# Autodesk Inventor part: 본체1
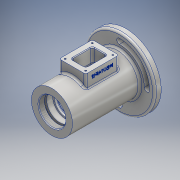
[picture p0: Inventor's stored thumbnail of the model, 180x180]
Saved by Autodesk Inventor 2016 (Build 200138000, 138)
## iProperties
Created: 2017-05
Part Number: 본체1
Material: 알루미늄 6061
Document SubType Name: Modeling
Designer: USER
Density: 2.7 g/cm^3
Appearance: 알루미늄 - 평지
Mass: 679.78 g
Surface Area: 617.383 cm^2
Volume: 251.77 cm^3
Author: USER
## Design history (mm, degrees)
sketch "스케치1"
  geometry: L1 (0, 0)-(-19.565, 0); L2 (0, 0)-(0, 31); L3 (0, 31)-(102, 31); L4 (102, 31)-(102, 53); L5 (102, 53)-(112, 53); L6 (112, 53)-(112, 31); L7 (112, 31)-(115, 31); L8 (115, 31)-(115, 0); L9 (115, 0)-(0, 0)
  constraints: 18 end point, 6 perpendicular, 2 point on line, 1 horizontal, 1 vertical
  dimensions: "d0" = 62 diameter of L3 L1; "d1" = 106 diameter of L5 L1; "d2" = 13 distance between parallel lines of L8 L4; "d3" = 3 distance of L6.end L7.end; "d4" = 115 distance between parallel lines of L2 L8
revolve "회전1" sketch "스케치1" stored, may be unused: angle "d5" = 90 deg
sketch "스케치3"
  geometry: 2 further points
  constraints: 1 coincident
hole "구멍1" sketch "스케치3" at (0, 0) diameter "d6" = 40.376; stored, may be unused: countersink angle "d10" = 90 deg, drill point angle "d12" = 118 deg; dims "d7" = 9, "d8" = 4, "d9" = 2, "d11" = 9
sketch "스케치4"
  geometry: L1 (9, 20.188)-(9, -20.188) reference; L2 (9, 0)-(9, 24); L3 (9, 24)-(12, 24); L4 (12, 24)-(12, 20); L5 (12, 20)-(21, 20); L6 (21, 20)-(21, 17.5); L7 (21, 17.5)-(24.25, 17.5); L8 (24.25, 17.5)-(24.25, 18.5); L9 (24.25, 18.5)-(26, 18.5); L10 (26, 18.5)-(26, 17.5); L11 (26, 17.5)-(37, 17.5); L12 (37, 17.5)-(37, 26); L13 (37, 26)-(75, 26); L14 (75, 26)-(75, 17.5); L15 (75, 17.5)-(86, 17.5); L16 (86, 17.5)-(86, 16.5); L17 (86, 16.5)-(91, 16.5); L18 (91, 16.5)-(91, 10); L19 (91, 10)-(93.7, 10); L20 (93.7, 10)-(93.7, 12.5); L21 (93.7, 12.5)-(100.3, 12.5); L22 (100.3, 12.5)-(101, 12.904); L23 (101, 12.904)-(101, 16); L24 (101, 16)-(115, 22); L25 (0, 0)-(-21.161, 0); L26 (0, -20.188)-(0, 20.188) reference; L27 (0, -31)-(0, 31) reference; L28 (115, 22)-(115, 0); L29 (115, -31)-(115, 31) reference; L30 (115, 0)-(9, 0)
  constraints: 52 end point, 16 perpendicular, 4 point on line, 3 vertical, 2 midpoint, 1 horizontal
  dimensions: "d13" = 48 diameter of L3 L25; "d14" = 3 distance of L2.end L3.end; "d15" = 40 diameter of L5 L25; "d16" = 35 diameter of L7 L25; "d17" = 21 distance from line of L5.end L26; "d18" = 26 distance between parallel lines of L26 L10; "d19" = 11 distance of L10.end L11.end; "d20" = 38 distance of L12.end L13.end; "d21" = 52 diameter of L13 L25; "d22" = 44 diameter of L24.end L25; "d23" = 32 diameter of L23.end L25; "d24" = 14 horizontal distance of L24.end L23.end; "d25" = 30 deg angle of L21 L22; "d26" = 33 diameter of L17 L25; "d27" = 115 distance from line of L27 L24.end; "d28" = 24 distance from line of L24.end L18; "d29" = 0.7 horizontal distance of L21.end L22.end; "d30" = 25 diameter of L21 L25; "d31" = 20 diameter of L19 L25; "d32" = 2.7 distance of L18.end L19.end; "d33" = 37 diameter of L9 L25; "d34" = 1.75 distance of L8.end L9.end; "d35" = 11 distance of L14.end L15.end
revolve "회전2" sketch "스케치4" stored, may be unused: angle "d36" = 90 deg
node "작업 평면1"
sketch "스케치5"
  geometry: L1 (20, 81)-(-20, 81); L2 (-20, 81)-(-20, 31); L3 (-20, 31)-(20, 31); L4 (20, 31)-(20, 81); L5 (20, 81)-(-20, 31); L6 (-20, 81)-(20, 31); 3 further points
  constraints: 12 end point, 3 midpoint, 2 parallel, 1 horizontal, 1 perpendicular, 1 vertical alignment
  dimensions: "d38" = 50 distance of L1.end L2.end; "d39" = 40 distance of L1.start L1.end; "d40" = 56 distance of point (0, 0) point (0, 56)
extrude "돌출1" join sketch "스케치5" stored distance "d41" = 10; taper "d42" = 0 deg
sketch "스케치6"
  geometry: L1 (11, 40)-(-11, 40); L2 (-11, 40)-(-11, 72); L3 (-11, 72)-(11, 72); L4 (11, 72)-(11, 40); L5 (11, 40)-(-11, 72); L6 (-11, 40)-(11, 72); 3 further points
  constraints: 12 end point, 3 midpoint, 2 parallel, 1 horizontal, 1 perpendicular, 1 vertical alignment
  dimensions: "d43" = 32 distance of L1.end L2.end; "d44" = 22 distance of L1.start L1.end; "d45" = 56 distance of point (0, 0) point (0, 56)
extrude "돌출2" cut sketch "스케치6" stored distance "d46" = 10; taper "d47" = 0 deg
sketch "스케치7"
  geometry: L1 (15.5, 76.5)-(-15.5, 76.5); L2 (-15.5, 76.5)-(-15.5, 35.5); L3 (-15.5, 35.5)-(15.5, 35.5); L4 (15.5, 35.5)-(15.5, 76.5); L5 (15.5, 76.5)-(-15.5, 35.5); L6 (-15.5, 76.5)-(15.5, 35.5); 7 further points
  constraints: 12 end point, 4 coincident, 3 midpoint, 2 parallel, 1 horizontal, 1 perpendicular, 1 vertical alignment
  dimensions: "d48" = 56 distance of point (0, 0) point (0, 56); "d49" = 41 distance of L1.end L2.end; "d50" = 31 distance of L2.end L3.end
hole "구멍2" sketch "스케치7" at (-15.5, 35.5), (-15.5, 76.5), (15.5, 76.5), (15.5, 35.5) diameter "d51" = 2.459; stored, may be unused: countersink angle "d55" = 90 deg, drill point angle "d57" = 118 deg; dims "d52" = 6, "d53" = 4, "d54" = 2, "d56" = 8
sketch "스케치8"
  geometry: L1 (75, -31)-(13, -31) reference; L2 (0, 0)-(0, 50) reference; 2 further points
  constraints: 1 other
  dimensions: "d58" = 56 distance from line of L1 point (8, 25); "d59" = 8 distance from line of point (8, 25) L2
feature "엠보싱1" sketch "스케치8" dims "d60" = 0.5, "d61" = 0
sketch "스케치9"
  geometry: A1 r 41.5 centre (0, 0) between (0, -41.5) and (41.5, 0); A2 r 45.5 centre (0, 0) between (0, -45.5) and (45.5, 0); A3 r 37.5 centre (0, 0) between (0, -37.5) and (37.5, 0); A4 r 4 centre (0, -41.5) between (0, -37.5) and (0, -45.5); A5 r 4 centre (41.5, 0) between (45.5, 0) and (37.5, 0); A6 r 41.5 centre (0, 0) between (0, 41.5) and (-41.5, 0); A7 r 45.5 centre (0, 0) between (0, 45.5) and (-45.5, 0); A8 r 37.5 centre (0, 0) between (0, 37.5) and (-37.5, 0); A9 r 4 centre (0, 41.5) between (0, 37.5) and (0, 45.5); A10 r 4 centre (-41.5, 0) between (-45.5, 0) and (-37.5, 0); 1 further point
  constraints: 20 point on circle, 10 centre point, 8 tangent, 2 coincident, 2 horizontal alignment, 2 vertical alignment
  dimensions: "d62" = 4 radius of A4; "d63" = 4 radius of A10; "d65" = 83 diameter of A1; "d66" = 83 diameter of A6
extrude "돌출3" cut sketch "스케치9" distance "d67" = 17.25; taper "d68" = 0 deg
fillet "모깎기1" dims "d69" = 3
fillet "모깎기2" dims "d70" = 0.3
fillet "모깎기3" dims "d71" = 0.3
chamfer "모따기1" distance "d72" = 1; stored, may be unused: second distance "d73" = 2, angle "d74" = 45 deg
fillet "모깎기4" dims "d75" = 3
fillet "모깎기5" dims "d76" = 3
fillet "모깎기6" dims "d77" = 3
chamfer "모따기2" distance "d78" = 1; stored, may be unused: second distance "d79" = 2, angle "d80" = 45 deg
chamfer "모따기3" distance "d81" = 1; stored, may be unused: second distance "d82" = 2, angle "d83" = 45 deg
fillet "모깎기7" dims "d84" = 3
chamfer "모따기4" distance "d85" = 1; stored, may be unused: second distance "d86" = 2, angle "d87" = 45 deg
node "솔리드1"
other parameters: "d37" = 44
